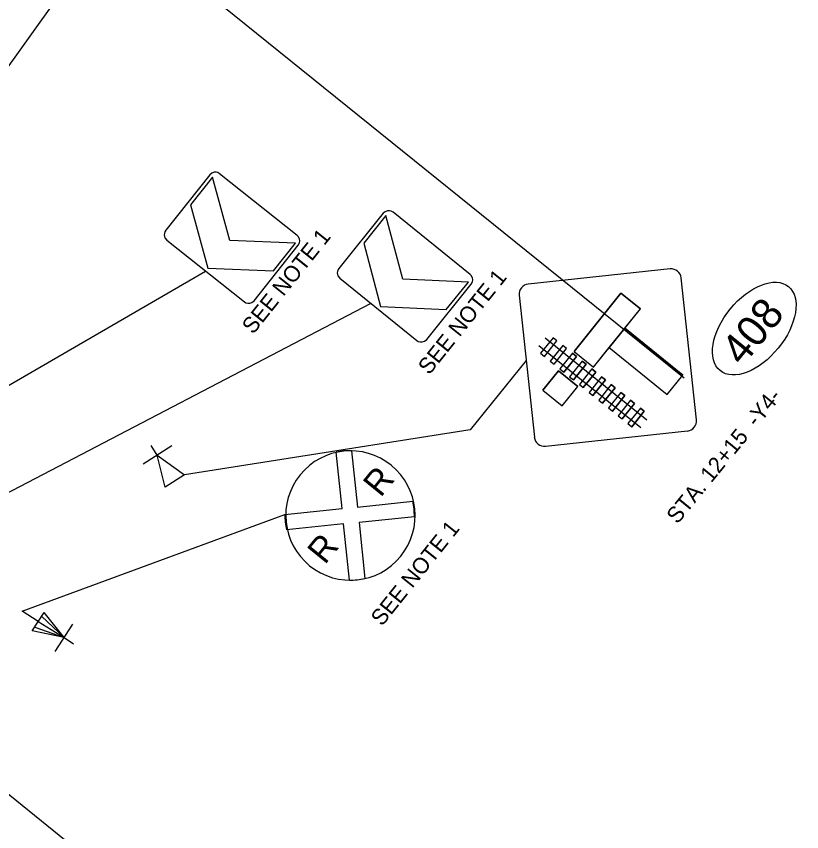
# Model space of a CAD drawing. Extents: x 1487362 to 2061618, y 497428 to 671257.
# Drawn here: x 1488928.7 to 1489086.1, y 499111.2 to 499274.8 of the extents above; entities that cross this region are included whole.
import ezdxf

# ---------------------------------------------------------------- set-up
doc = ezdxf.new("R2010")
doc.units = 0
for name, color, linetype in [('Exist Sign E Chevron Left', 7, 'Continuous'), ('Exist Support 1', 7, 'Continuous'), ('Prop Sign E', 7, 'Continuous'), ('Prop Sign E Ped Crossing CELL', 7, 'Continuous'), ('Prop Support One', 7, 'Continuous'), ('Scratch_Level_1', 7, 'Continuous'), ('Text', 7, 'Continuous')]:
    doc.layers.add(name, color=color, linetype=linetype)

msp = doc.modelspace()

# ---------------------------------------------------------------- linework, layer by layer
at = {"layer": 'Exist Sign E Chevron Left'}
for p, q in [((1488971.47, 499229.78), (1488971.47, 499229.78)), ((1489006.15, 499222.05), (1489006.15, 499222.05)), ((1488995.89, 499187.64), (1488997.06, 499176.34)), ((1488993.97, 499176.02), (1488992.8, 499187.36)), ((1488982.52, 499174.84), (1488993.97, 499176.02)), ((1488997.06, 499176.34), (1489008.17, 499177.49)), ((1489008.48, 499174.4), (1488997.38, 499173.26)), ((1488994.29, 499172.94), (1488982.84, 499171.75)), ((1488995.45, 499161.67), (1488994.29, 499172.94)), ((1488997.38, 499173.26), (1488998.53, 499162.03))]:
    msp.add_line(p, q, dxfattribs=at)
for points in [[(1488984.98, 499230.82), (1488969.44, 499243.18), (1488969.05, 499243.41), (1488968.75, 499243.47), (1488968.35, 499243.47), (1488967.85, 499243.29), (1488967.45, 499242.95), (1488958.63, 499231.85), (1488958.42, 499231.51), (1488958.35, 499231.23), (1488958.33, 499230.93), (1488958.37, 499230.61), (1488958.47, 499230.34), (1488958.85, 499229.86), (1488974.39, 499217.5), (1488974.66, 499217.32), (1488975.07, 499217.21), (1488975.48, 499217.22), (1488975.9, 499217.34), (1488976.39, 499217.73), (1488985.21, 499228.83), (1488985.47, 499229.32), (1488985.51, 499229.71), (1488985.46, 499230.14), (1488985.2, 499230.58), (1488984.98, 499230.82)], [(1489019.66, 499223), (1489004.21, 499235.46), (1489003.82, 499235.7), (1489003.52, 499235.76), (1489003.12, 499235.76), (1489002.62, 499235.58), (1489002.22, 499235.25), (1488993.32, 499224.21), (1488993.11, 499223.87), (1488993.04, 499223.59), (1488993.01, 499223.29), (1488993.05, 499222.97), (1488993.15, 499222.7), (1488993.53, 499222.22), (1489008.98, 499209.76), (1489009.24, 499209.57), (1489009.66, 499209.46), (1489010.07, 499209.46), (1489010.49, 499209.58), (1489010.98, 499209.97), (1489019.88, 499221.01), (1489020.14, 499221.5), (1489020.19, 499221.88), (1489020.13, 499222.32), (1489019.88, 499222.76), (1489019.66, 499223)]]:
    msp.add_lwpolyline(points, dxfattribs=at)
for points in [[(1488984.66, 499229.27), (1488971.47, 499229.78), (1488968.01, 499242.51), (1488963.6, 499236.96), (1488967.06, 499224.23), (1488980.25, 499223.72)], [(1489019.33, 499221.45), (1489006.15, 499222.05), (1489002.77, 499234.8), (1488998.32, 499229.28), (1489001.7, 499216.53), (1489014.88, 499215.93)]]:
    msp.add_lwpolyline(points, close=True, dxfattribs=at)
for centre, start, end in [((1488995.67, 499174.64), 320.896, 140.896), ((1488995.5, 499174.66), 88.2806, 102.0012), ((1488995.67, 499174.64), 140.896, 320.896), ((1488995.5, 499174.66), 358.8695, 12.5905), ((1488995.5, 499174.66), 179.2028, 192.9208), ((1488995.5, 499174.66), 269.7907, 283.5116)]:
    msp.add_arc(centre, 12.98, start, end, dxfattribs=at)
at = {"layer": 'Exist Support 1'}
for p, q in [((1488890.68, 499179.59), (1488966.62, 499223.68)), ((1488908.03, 499169.31), (1488999.69, 499217.15)), ((1488929.81, 499155.48), (1488982.52, 499174.84)), ((1488933.08, 499153.35), (1488929.81, 499155.48)), ((1488931.87, 499151.48), (1488934.27, 499155.19)), ((1488938.25, 499150.14), (1488934.27, 499155.19)), ((1488933.08, 499153.35), (1488938.25, 499150.14)), ((1488933.75, 499154.4), (1488938.25, 499150.14)), ((1488938.25, 499150.14), (1488931.87, 499151.48)), ((1488932.36, 499152.24), (1488938.25, 499150.14)), ((1488936.46, 499147.35), (1488940.02, 499152.88)), ((1488938.25, 499150.14), (1488940.13, 499148.93))]:
    msp.add_line(p, q, dxfattribs=at)
at = {"layer": 'Prop Sign E'}
msp.add_ellipse((1489076.63, 499212.13), major_axis=(-6.85, -8.43), ratio=0.571429, dxfattribs=at)
at = {"layer": 'Prop Sign E Ped Crossing CELL'}
for p, q in [((1489059.75, 499224.09), (1489031.3, 499221.05)), ((1489065.04, 499193.83), (1489062, 499222.28)), ((1489029.49, 499218.8), (1489032.54, 499190.35)), ((1489040.49, 499207.56), (1489049.91, 499219.23)), ((1489049.91, 499219.23), (1489040.49, 499207.56)), ((1489049.91, 499219.23), (1489053.8, 499216.09)), ((1489053.8, 499216.09), (1489049.91, 499219.23)), ((1489044.38, 499204.42), (1489053.8, 499216.09)), ((1489050.66, 499212.2), (1489047.52, 499208.31)), ((1489050.66, 499212.2), (1489062.34, 499202.78)), ((1489062.34, 499202.78), (1489050.66, 499212.2)), ((1489033.46, 499208.73), (1489053.86, 499192.28)), ((1489036.29, 499210.3), (1489033.78, 499207.19)), ((1489034.55, 499206.56), (1489037.06, 499209.68)), ((1489034.72, 499210.29), (1489055.12, 499193.83)), ((1489038.23, 499208.74), (1489035.72, 499205.62)), ((1489037.06, 499209.68), (1489036.29, 499210.3)), ((1489039.01, 499208.11), (1489038.23, 499208.74)), ((1489033.78, 499207.19), (1489034.55, 499206.56)), ((1489036.5, 499204.99), (1489039.01, 499208.11)), ((1489040.18, 499207.17), (1489037.67, 499204.05)), ((1489040.18, 499207.17), (1489037.67, 499204.05)), ((1489040.18, 499207.17), (1489040.96, 499206.54)), ((1489040.96, 499206.54), (1489040.18, 499207.17)), ((1489040.49, 499207.56), (1489044.38, 499204.42)), ((1489040.49, 499207.56), (1489044.38, 499204.42)), ((1489047.52, 499208.31), (1489059.2, 499198.89)), ((1489047.52, 499208.31), (1489059.2, 499198.89)), ((1489035.72, 499205.62), (1489036.5, 499204.99)), ((1489040.96, 499206.54), (1489038.45, 499203.42)), ((1489038.45, 499203.42), (1489040.96, 499206.54)), ((1489042.12, 499205.6), (1489039.61, 499202.48)), ((1489042.12, 499205.6), (1489039.61, 499202.48)), ((1489042.12, 499205.6), (1489039.61, 499202.48)), ((1489042.12, 499205.6), (1489042.9, 499204.97)), ((1489042.9, 499204.97), (1489042.12, 499205.6)), ((1489037.67, 499204.05), (1489038.45, 499203.42)), ((1489037.67, 499204.05), (1489038.45, 499203.42)), ((1489042.9, 499204.97), (1489040.39, 499201.86)), ((1489040.39, 499201.86), (1489042.9, 499204.97)), ((1489044.07, 499204.03), (1489041.56, 499200.91)), ((1489044.07, 499204.03), (1489041.56, 499200.91)), ((1489044.07, 499204.03), (1489044.85, 499203.4)), ((1489044.85, 499203.4), (1489044.07, 499204.03)), ((1489034.21, 499199.77), (1489037.35, 499203.66)), ((1489037.35, 499203.66), (1489034.21, 499199.77)), ((1489037.35, 499203.66), (1489041.25, 499200.52)), ((1489041.25, 499200.52), (1489037.35, 499203.66)), ((1489039.61, 499202.48), (1489040.39, 499201.86)), ((1489039.61, 499202.48), (1489040.39, 499201.86)), ((1489044.85, 499203.4), (1489042.34, 499200.29)), ((1489042.34, 499200.29), (1489044.85, 499203.4)), ((1489046.02, 499202.46), (1489043.51, 499199.34)), ((1489046.02, 499202.46), (1489043.51, 499199.34)), ((1489046.02, 499202.46), (1489046.79, 499201.83)), ((1489046.79, 499201.83), (1489046.02, 499202.46)), ((1489059.2, 499198.89), (1489062.34, 499202.78)), ((1489059.2, 499198.89), (1489062.34, 499202.78)), ((1489038.11, 499196.63), (1489041.25, 499200.52)), ((1489038.11, 499196.63), (1489041.25, 499200.52)), ((1489041.56, 499200.91), (1489042.34, 499200.29)), ((1489041.56, 499200.91), (1489042.34, 499200.29)), ((1489046.79, 499201.83), (1489044.28, 499198.72)), ((1489044.28, 499198.72), (1489046.79, 499201.83)), ((1489047.96, 499200.89), (1489045.45, 499197.77)), ((1489047.96, 499200.89), (1489045.45, 499197.77)), ((1489047.96, 499200.89), (1489048.74, 499200.26)), ((1489048.74, 499200.26), (1489047.96, 499200.89)), ((1489034.21, 499199.77), (1489038.11, 499196.63)), ((1489034.21, 499199.77), (1489038.11, 499196.63)), ((1489043.51, 499199.34), (1489044.28, 499198.72)), ((1489043.51, 499199.34), (1489044.28, 499198.72)), ((1489048.74, 499200.26), (1489046.23, 499197.15)), ((1489046.23, 499197.15), (1489048.74, 499200.26)), ((1489049.91, 499199.32), (1489047.4, 499196.21)), ((1489049.91, 499199.32), (1489047.4, 499196.21)), ((1489049.91, 499199.32), (1489050.69, 499198.69)), ((1489050.69, 499198.69), (1489049.91, 499199.32)), ((1489045.45, 499197.77), (1489046.23, 499197.15)), ((1489045.45, 499197.77), (1489046.23, 499197.15)), ((1489050.69, 499198.69), (1489048.18, 499195.58)), ((1489048.18, 499195.58), (1489050.69, 499198.69)), ((1489051.85, 499197.75), (1489049.34, 499194.64)), ((1489051.85, 499197.75), (1489049.34, 499194.64)), ((1489051.85, 499197.75), (1489052.63, 499197.12)), ((1489052.63, 499197.12), (1489051.85, 499197.75)), ((1489047.4, 499196.21), (1489048.18, 499195.58)), ((1489047.4, 499196.21), (1489048.18, 499195.58)), ((1489052.63, 499197.12), (1489050.12, 499194.01)), ((1489050.12, 499194.01), (1489052.63, 499197.12)), ((1489053.8, 499196.18), (1489051.29, 499193.07)), ((1489053.8, 499196.18), (1489051.29, 499193.07)), ((1489053.8, 499196.18), (1489054.58, 499195.55)), ((1489054.58, 499195.55), (1489053.8, 499196.18)), ((1489049.34, 499194.64), (1489050.12, 499194.01)), ((1489049.34, 499194.64), (1489050.12, 499194.01)), ((1489054.58, 499195.55), (1489052.07, 499192.44)), ((1489052.07, 499192.44), (1489054.58, 499195.55)), ((1489051.29, 499193.07), (1489052.07, 499192.44)), ((1489051.29, 499193.07), (1489052.07, 499192.44)), ((1489034.78, 499188.54), (1489063.23, 499191.59))]:
    msp.add_line(p, q, dxfattribs=at)
msp.add_lwpolyline([(1489044.38, 499204.42), (1489047.52, 499208.31), (1489050.66, 499212.2), (1489053.8, 499216.09)], dxfattribs=at)
for centre, start, end in [((1489059.97, 499222.06), 6.1142, 96.1142), ((1489031.52, 499219.02), 96.1142, 186.1142), ((1489063.01, 499193.61), 276.1142, 6.1142), ((1489034.56, 499190.57), 186.1142, 276.1142)]:
    msp.add_arc(centre, 2.04, start, end, dxfattribs=at)
at = {"layer": 'Prop Support One'}
for p, q in [((1488911.23, 499242.69), (1488975.77, 499332.48)), ((1488959.82, 499188.62), (1488954.1, 499184.94)), ((1488956.94, 499186.77), (1488955.68, 499188.71)), ((1488958.52, 499180.3), (1488956.94, 499186.77)), ((1488956.94, 499186.77), (1488962.37, 499182.77)), ((1488962.37, 499182.77), (1488958.52, 499180.3))]:
    msp.add_line(p, q, dxfattribs=at)
msp.add_lwpolyline([(1489030.89, 499205.72), (1489019.68, 499191.82), (1488962.37, 499182.77)], dxfattribs=at)
at = {"layer": 'Scratch_Level_1'}
for p, q in [((1489062.58, 499202.19), (1488751.22, 499453.29)), ((1488657.05, 499336.52), (1488968.42, 499085.42))]:
    msp.add_line(p, q, dxfattribs=at)

# ---------------------------------------------------------------- texts
at = {"layer": 'Exist Sign E Chevron Left'}
for p in [(1489001.71, 499178.11), (1488990.53, 499164.63)]:
    msp.add_text('R', height=5, rotation=50.896, dxfattribs=at).set_placement(p)
at = {"layer": 'Prop Sign E'}
msp.add_text('408', height=6.136, rotation=50.9062, dxfattribs=at).set_placement((1489074.3, 499204.4))
at = {"layer": 'Text'}
for s, rotation, p in [('SEE NOTE 1', 51.3435, (1488976.14, 499210.82)), ('SEE NOTE 1', 51.3435, (1489011.45, 499202.68)), ('STA. 12+15  -Y4-', 50.7424, (1489061.24, 499172.77)), ('SEE NOTE 1', 51.3435, (1489001.98, 499152.28))]:
    msp.add_text(s, height=3.2, rotation=rotation, dxfattribs=at).set_placement(p)

doc.saveas('drawing.dxf')
